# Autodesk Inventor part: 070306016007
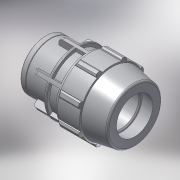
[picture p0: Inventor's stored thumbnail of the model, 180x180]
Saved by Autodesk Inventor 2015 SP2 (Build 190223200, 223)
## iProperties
Created: 2017-02
Part Number: 070306016007
Material: PVC-Piping
Description: PLASSON FEMALE ADAPTOR 16-3/4"
Document SubType Name: Modeling
Designer: KIM
Mass: 92.6774 g
Surface Area: 199.44 cm^2
Volume: 66.1981 cm^3
Density: 1.4 g/cm^3
Appearance: Smooth - White
Author: KIM
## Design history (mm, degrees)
derived "07030.ipt"
feature "Solid1::07030.ipt"
tag "TaggingFeature1"
body "Solid1"
other parameters: "d2" = 16, "d4" = 10.71429, "d5" = 18.75, "d7" = 39, "d9" = 10.71429, "d11" = 2.14286, "d12" = 31.2, "d13" = 120 deg, "d14" = 24, "d15" = 12 deg, "d16" = 35.1, "d18" = 0.8, "d19" = 35 deg, "d20" = 17.5 deg, "d21" = 36.27, "d23" = 0, "d25" = 360 deg, "d27" = 0.78, "d34" = 1.95, "d35" = 22.5, "d36" = 0, "d42" = 18.75, "d43" = 1.17, "d46" = 0.48, "d49" = 53, "d51" = 75, "d53" = 0.32, "d55" = 360 deg, "d61" = 19, "d62" = 12.8, "d63" = 24.117, "d64" = 25, "d65" = 1.95, "d66" = 0.5, "d67" = 1, "d68" = 5.7, "d69" = 28.08, "d70" = 0.975, "d_" = 16, "E_" = 39, "H_" = 75, "l_" = 53, "l_2" = 19, "Rp_" = 24.117
